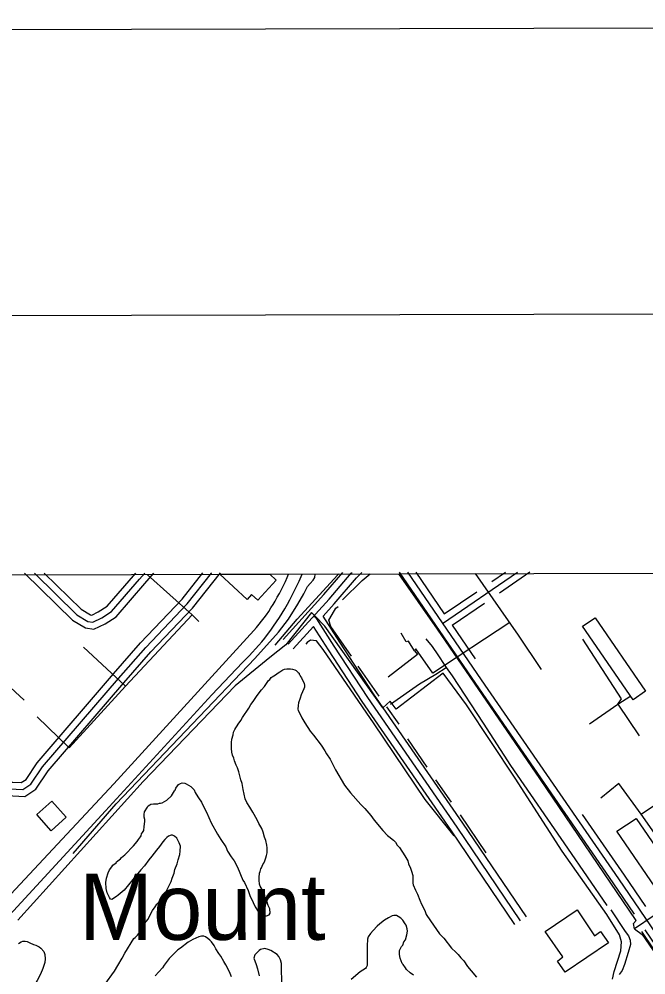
# Model space of a CAD drawing. Extents: x 3355724 to 3393621, y 594744 to 620174.
# Drawn here: x 3384041 to 3385411, y 617501 to 619590 of the extents above; entities that cross this region are included whole.
import ezdxf

# ---------------------------------------------------------------- set-up
doc = ezdxf.new("R2010")
doc.units = 0
for name, color, linetype in [('G-ANNO-NPLT', 7, 'Continuous'), ('V-ANNO-SYMB', 7, 'Continuous'), ('V-BLDG-OTLN', 7, 'Continuous'), ('V-GRID-FRAM', 7, 'Continuous'), ('V-RAIL-TRAK', 7, 'Continuous'), ('V-ROAD-CNTR', 7, 'Continuous'), ('V-SITE-OTLN', 7, 'Continuous'), ('V-SITE-VEGE', 7, 'Continuous'), ('V-TOPO-GNAM-IDEN', 7, 'Continuous'), ('V-TOPO-SHOR', 7, 'Continuous'), ('V-UTIL-LINE', 7, 'Continuous')]:
    doc.layers.add(name, color=color, linetype=linetype)

msp = doc.modelspace()

# ---------------------------------------------------------------- linework, layer by layer
at = {"layer": 'G-ANNO-NPLT'}
msp.add_lwpolyline([(3356370.8, 595327.7), (3393037.4, 595423.7), (3392974.1, 619590.2), (3356307.6, 619494.2)], close=True, dxfattribs=at)
at = {"layer": 'V-ANNO-SYMB'}
msp.add_lwpolyline([(3359119.3, 595959.9), (3392202.4, 596046.5), (3392142.4, 618963), (3359059.3, 618876.4), (3359119.3, 595959.9)], dxfattribs=at)
at = {"layer": 'V-BLDG-OTLN'}
for p, q in [((3384479.8, 618376.4), (3384480, 618376.7)), ((3384539.4, 618321.6), (3384479.8, 618376.4)), ((3384480, 618376.7), (3384589, 618376.9)), ((3384589, 618376.9), (3384603.3, 618363.8)), ((3384603.3, 618363.8), (3384562.7, 618319.7)), ((3384549.2, 618332.2), (3384539.4, 618321.6)), ((3384562.7, 618319.7), (3384549.2, 618332.2))]:
    msp.add_line(p, q, dxfattribs=at)
for points in [[(3385300.2, 618281), (3385410.4, 618121.1), (3385383.1, 618102.3), (3385272.4, 618262.9)], [(3384112.8, 617880.6), (3384144.4, 617845.3), (3384111.4, 617815.8), (3384079.8, 617851.1)], [(3385389.4, 617842.8), (3385491.7, 617694.2), (3385450.1, 617664.7), (3385347.2, 617815.1)], [(3385328.9, 617570.9), (3385234.4, 617506.5), (3385217.5, 617530.8), (3385229.4, 617539.8), (3385190.9, 617595.7), (3385261, 617642.7), (3385299, 617586.2), (3385311.5, 617595.3)]]:
    msp.add_lwpolyline(points, close=True, dxfattribs=at)
at = {"layer": 'V-GRID-FRAM'}
msp.add_lwpolyline([(3359807.6, 618312.1), (3391397.2, 618394.8), (3391452.7, 600211.2), (3359847.2, 600128.5), (3359807.6, 618312.1)], dxfattribs=at)
at = {"layer": 'V-RAIL-TRAK'}
for points in [[(3383676.2, 617348.3), (3383804.6, 617451.3), (3383824.1, 617467.9), (3383850.7, 617493.2), (3383878.8, 617523.3), (3384248.4, 617918.6), (3384554.6, 618253.8), (3384560.3, 618260.4), (3384566, 618267.2), (3384571.4, 618274), (3384576.7, 618281), (3384581.8, 618288.2), (3384586.8, 618295.4), (3384591.6, 618302.8), (3384596.2, 618310.2), (3384600.6, 618317.8), (3384605.5, 618326.2), (3384610.2, 618334.7), (3384614.7, 618343.3), (3384619, 618352.1), (3384623.2, 618360.9), (3384627.1, 618369.8), (3384630.1, 618377.1)], [(3383995.1, 617604.4), (3384230.3, 617859), (3384462.3, 618112.8), (3384529.5, 618183.9), (3384536.8, 618191.1), (3384544.1, 618198.4), (3384551.2, 618205.9), (3384558.1, 618213.5), (3384564.9, 618221.2), (3384571.6, 618229), (3384578, 618237), (3384584.4, 618245.2), (3384591.1, 618254.2), (3384597.6, 618263.3), (3384604, 618272.6), (3384610.2, 618282), (3384616.2, 618291.5), (3384622, 618301.2), (3384627.6, 618310.9), (3384633.1, 618320.7), (3384638.4, 618330.7), (3384643.4, 618340.7), (3384648.3, 618350.9), (3384653, 618361.1), (3384657.4, 618371.4), (3384659.8, 618377.1)]]:
    msp.add_lwpolyline(points, dxfattribs=at)
at = {"layer": 'V-ROAD-CNTR'}
for points in [[(3383502.6, 618377.2), (3383572.1, 618314.1), (3384020.6, 617907.3), (3384049.9, 617906), (3384067.3, 617917.3), (3384092.7, 617955.6), (3384258.8, 618148.9), (3384318, 618216.7), (3384408.7, 618312.1), (3384461.5, 618379.1), (3384462, 618379.7)], [(3383524.9, 618377.2), (3383582.2, 618325.2), (3384026.6, 617922), (3384045.7, 617921.2), (3384056.5, 617928.2), (3384080.7, 617964.6), (3384247.5, 618158.7), (3384306.9, 618226.8), (3384397.4, 618321.9), (3384442.8, 618379.6)], [(3383879.4, 618015.1), (3384014.5, 617892.5), (3384054, 617890.8), (3384078.1, 617906.5), (3384104.7, 617946.5), (3384270.2, 618139.1), (3384329.1, 618206.6), (3384420.1, 618302.2), (3384481.1, 618379.7)], [(3384053.3, 618378.6), (3384158.4, 618275.9), (3384186.7, 618259.1), (3384204.9, 618256.2), (3384229.3, 618268.5), (3384253.4, 618283.6), (3384316, 618356.1), (3384336, 618379.3)], [(3384074.7, 618378.7), (3384167.6, 618287.9), (3384191.9, 618273.5), (3384202.5, 618271.8), (3384221.9, 618281.6), (3384243.5, 618295.2), (3384304.7, 618365.9), (3384316.2, 618379.3)], [(3384096.1, 618378.7), (3384176.8, 618299.9), (3384197.1, 618287.9), (3384200.1, 618287.4), (3384214.5, 618294.7), (3384233.7, 618306.7), (3384296.4, 618379.2)], [(3384618.2, 618233.9), (3384707.4, 618332), (3384748.8, 618380.4)], [(3384629.3, 618223.8), (3384718.6, 618322), (3384767.3, 618378.9), (3384768.8, 618380.5)], [(3384705.5, 618285.2), (3384729.9, 618312.1), (3384778.3, 618368.8), (3384790.1, 618380.5)], [(3384871.9, 618380.8), (3385038.3, 618137.5), (3385338.8, 617702), (3385385.6, 617633.2)], [(3384890, 618380.8), (3385050.7, 618146), (3385351.1, 617710.5), (3385675.8, 617233.1), (3385948.8, 616834.8), (3386180.2, 616499.2)], [(3384908.1, 618380.8), (3384970.4, 618289.8)], [(3384966.5, 618269), (3385130.6, 618381.4)], [(3385074.1, 618360.9), (3385104, 618381.4)], [(3385090.9, 618336), (3385157.3, 618381.5)], [(3384970.4, 618289.8), (3385041.3, 618338.4)], [(3384987.4, 618265.1), (3385058.1, 618313.5)], [(3385137.3, 617619.2), (3384998.7, 617823.9), (3384803.6, 618106.8), (3384729.8, 618219.6), (3384686.6, 618286.8), (3384685.6, 618282.3)], [(3385149.8, 617627.6), (3385011.1, 617832.4), (3384816.1, 618115.2), (3384742.4, 618227.8), (3384705.5, 618285.2)], [(3384640.4, 618213.7), (3384684.6, 618262.3)], [(3385124.9, 617610.8), (3384986.3, 617815.4), (3384791.2, 618098.4), (3384717.2, 618211.5), (3384684.6, 618262.3)], [(3384987.4, 618265.1), (3385037.7, 618191.5)], [(3385272, 617851.5), (3385363.5, 617719), (3385410.4, 617650)], [(3385408.6, 617599.4), (3385663.4, 617224.7), (3385936.4, 616826.3), (3386031.5, 616688.4)]]:
    msp.add_lwpolyline(points, dxfattribs=at)
at = {"layer": 'V-SITE-OTLN'}
for p, q in [((3381827, 618369.7), (3388510.8, 618387.2)), ((3384680.2, 618293.3), (3384623.9, 618221.9)), ((3384687.7, 618285.5), (3384680.2, 618293.3)), ((3384709.6, 618263), (3384687.7, 618285.5)), ((3384836, 618084.7), (3384709.6, 618263)), ((3384623.9, 618221.9), (3384589.5, 618194.9)), ((3384589.5, 618194.9), (3384513.5, 618132.3)), ((3384968, 618160.1), (3384865.3, 618081.9)), ((3385019.2, 618091.2), (3384968, 618160.1)), ((3384513.5, 618132.3), (3384312.4, 617923.4)), ((3384852, 618099.2), (3384836, 618084.7)), ((3384865.3, 618081.9), (3384852, 618099.2)), ((3385125.2, 617930.7), (3385019.2, 618091.2)), ((3385228.2, 617770.8), (3385125.2, 617930.7)), ((3384312.4, 617923.4), (3384038.5, 617620.4)), ((3385325.7, 617632.9), (3385228.2, 617770.8)), ((3385353.4, 617588.4), (3385325.7, 617632.9)), ((3385357.7, 617572.9), (3385353.4, 617588.4)), ((3385356, 617553.2), (3385357.7, 617572.9)), ((3385341.9, 617508.3), (3385356, 617553.2)), ((3385337.9, 617491.6), (3385341.9, 617508.3))]:
    msp.add_line(p, q, dxfattribs=at)
at = {"layer": 'V-SITE-VEGE'}
for points in [[(3384582.5, 617662), (3384576.8, 617674.3), (3384574.5, 617681.5), (3384572.3, 617687.1), (3384568.3, 617694.3), (3384566.6, 617698.8), (3384566, 617707.7), (3384566, 617713.3), (3384566.5, 617722.8), (3384568.1, 617726.7), (3384569.8, 617732.3), (3384571.4, 617734.6), (3384574.2, 617741.8), (3384576.4, 617744.6), (3384578, 617749.7), (3384580.8, 617756.4), (3384581.9, 617761.4), (3384583.5, 617767.6), (3384583.4, 617778.7), (3384582.9, 617784.3), (3384580.6, 617794.3), (3384577.7, 617801.6), (3384574.9, 617812.7), (3384571.5, 617820.5), (3384565.3, 617831.6), (3384561.3, 617840), (3384552.3, 617856.1), (3384550, 617860), (3384545.5, 617867.3), (3384538.8, 617877.8), (3384535.4, 617885.6), (3384530.8, 617905.7), (3384528.5, 617919.1), (3384525.6, 617926.9), (3384523.3, 617938.6), (3384521.6, 617944.7), (3384518.8, 617953.6), (3384515.9, 617959.2), (3384512, 617968.6), (3384510.3, 617974.8), (3384508, 617980.9), (3384506.3, 617987.6), (3384505.7, 617995.4), (3384505.6, 618008.8), (3384506.1, 618016.1), (3384508.8, 618025.6), (3384509.9, 618031.2), (3384512.7, 618037.3), (3384514.9, 618040.7), (3384518.2, 618045.2), (3384520.4, 618049.1), (3384526, 618056.9), (3384529.8, 618063.7), (3384543.1, 618083.8), (3384547.5, 618091.7), (3384552.5, 618098.4), (3384561.9, 618111.8), (3384571.3, 618124.2), (3384577.4, 618131.5), (3384586.3, 618144.4), (3384589.1, 618146.6), (3384592.4, 618150.6), (3384594.6, 618152.2), (3384601.3, 618156.7), (3384607.4, 618160.7), (3384611.3, 618163.5), (3384617.4, 618167.4), (3384621.3, 618169.1), (3384626.3, 618169.7), (3384634.7, 618169.8), (3384638.6, 618169.2), (3384643.6, 618167.6), (3384647, 618165.9), (3384650.9, 618162.1), (3384653.2, 618160.4), (3384653.7, 618158.2), (3384654.9, 618156.5), (3384656.6, 618153.2), (3384658.8, 618150.4), (3384661.6, 618143.2), (3384664.5, 618138.1), (3384665.1, 618133.1), (3384665.1, 618129.8), (3384663.4, 618126.4), (3384657.9, 618113), (3384655.2, 618105.7), (3384651.9, 618095.1), (3384651.4, 618089.5), (3384650.3, 618081.7), (3384651.4, 618078.9), (3384655.4, 618070.5), (3384659.3, 618062.8), (3384665.5, 618051.6), (3384677.4, 618033.3), (3384684.7, 618024.9), (3384701.6, 618002.7), (3384709.5, 617990.5), (3384713.4, 617983.8), (3384721.3, 617972.1), (3384732.6, 617948.8), (3384752.3, 617915.4)], [(3384376.7, 617806.5), (3384374, 617806.5), (3384367.8, 617804.2), (3384363.9, 617800.8), (3384359.5, 617796.4), (3384355.1, 617791.3), (3384348.4, 617781.2), (3384341.8, 617773.4), (3384331.2, 617759.9), (3384324.6, 617752), (3384315.2, 617739.2), (3384307.4, 617730.7), (3384289.7, 617708.9), (3384270.8, 617685.9), (3384258.1, 617675.2), (3384254.2, 617671.8), (3384244.2, 617665.6), (3384240.8, 617666.1), (3384238.6, 617670), (3384233.5, 617680), (3384231.7, 617689.5), (3384231.1, 617702.9), (3384232.7, 617712.4), (3384236, 617723.6), (3384238.8, 617730.3), (3384243.7, 617737), (3384246.5, 617740.4), (3384253.2, 617746), (3384254.3, 617747.7), (3384263.2, 617754.5), (3384264.8, 617757.3), (3384272.1, 617763.5), (3384278.2, 617769.1), (3384286.5, 617777.5), (3384291.5, 617783.1), (3384299.2, 617792.6), (3384302.6, 617796.6), (3384304.2, 617799.4), (3384306.4, 617802.2), (3384308.1, 617805), (3384309.2, 617808.9), (3384310.8, 617811.7), (3384313.6, 617816.7), (3384314.7, 617825.1), (3384316.3, 617835.7), (3384316.2, 617840.2), (3384314.5, 617845.2), (3384314.5, 617851.3), (3384315.6, 617856.9), (3384321.7, 617867), (3384323.3, 617870.4), (3384327.2, 617872.6), (3384328.9, 617873.8), (3384335, 617874.4), (3384337.3, 617874.4), (3384342.3, 617875), (3384344.5, 617875), (3384347.9, 617876.1), (3384350.6, 617876.1), (3384354, 617876.7), (3384364, 617882.3), (3384374.6, 617891.9), (3384380.6, 617903.1), (3384382.3, 617904.8), (3384383.9, 617908.7), (3384390, 617916.6), (3384393.9, 617918.8), (3384397.8, 617920.5), (3384403.4, 617920), (3384406.8, 617918.3), (3384416.3, 617912.8), (3384423.6, 617905.6), (3384426.4, 617899.5), (3384432.1, 617890), (3384433.7, 617887.8), (3384439.9, 617878.3), (3384443.3, 617870), (3384451.2, 617856.1), (3384461.4, 617833.3), (3384475, 617808.2), (3384482.3, 617796.5), (3384493, 617780.4), (3384497, 617770.9), (3384504.9, 617758.7), (3384511.1, 617749.8), (3384518.4, 617735.9), (3384530.3, 617708.1), (3384533.7, 617702.5), (3384541.6, 617685.2), (3384545.6, 617674.1), (3384552.9, 617659.1), (3384556.9, 617649.6), (3384565.3, 617637.4), (3384572.1, 617631.8), (3384578.2, 617629.6), (3384582.1, 617629.7), (3384587.7, 617631.9), (3384589.9, 617635.9), (3384589.3, 617644.8), (3384585.9, 617652.6), (3384582.5, 617662)], [(3384752.3, 617915.4), (3384765.3, 617898.7), (3384788.3, 617873.2), (3384796.7, 617864.3), (3384810.2, 617849.3), (3384817.5, 617838.7), (3384836.1, 617816), (3384846.2, 617805.4), (3384849.6, 617803.2), (3384859.1, 617795.5), (3384863.6, 617790.5), (3384867.5, 617784.3), (3384872.6, 617779.3), (3384884.4, 617761), (3384890.6, 617749.9), (3384892.4, 617743.2), (3384896.3, 617733.7), (3384898.6, 617727.6), (3384901.4, 617718.1), (3384901.5, 617701.4), (3384902.1, 617697.5), (3384907.2, 617685.8), (3384911.7, 617677.4), (3384916.8, 617664.1)], [(3384228.5, 617479.6), (3384249.6, 617508.8), (3384256.8, 617521.1), (3384266.7, 617537.3), (3384272.2, 617548.5), (3384292.1, 617580.5), (3384294.9, 617582.2), (3384299.9, 617587.8), (3384306.6, 617595.6), (3384309.3, 617601.8), (3384315.9, 617613.6), (3384322.6, 617621.4), (3384327, 617629.8), (3384330.3, 617636.5), (3384333.1, 617641.6), (3384338.6, 617649.4), (3384342.5, 617655.6), (3384349.7, 617663.4), (3384353, 617668.5), (3384357.4, 617674.7), (3384360.2, 617678), (3384362.4, 617681.9), (3384364.6, 617687.5), (3384366.8, 617691.5), (3384373.4, 617704.9), (3384376.2, 617712.2), (3384380, 617722.8), (3384381.7, 617731.2), (3384386.6, 617743.5), (3384388.8, 617752.4), (3384392.6, 617764.2), (3384393.1, 617771.4), (3384394.2, 617782.1), (3384390.8, 617789.3), (3384386.3, 617799.9), (3384381.2, 617803.7), (3384376.7, 617806.5)], [(3384916.8, 617664.1), (3384920.8, 617655.2), (3384927.6, 617641.2), (3384931, 617632.9), (3384940, 617619), (3384960.3, 617590.6), (3384969.3, 617580.6), (3384986.1, 617559), (3384995.7, 617550.7), (3385000.7, 617545.1), (3385006.4, 617537.9), (3385013.1, 617531.2), (3385021.5, 617519), (3385028.9, 617509.5), (3385040.7, 617495.7)], [(3384903.3, 617500.4), (3384896, 617504.8), (3384888.2, 617512.1), (3384885.9, 617515.9), (3384880.3, 617523.2), (3384878.6, 617525.9), (3384874.1, 617537.1), (3384872.9, 617544.9), (3384872.8, 617553.8), (3384874.5, 617558.3), (3384876.7, 617562.8), (3384879.5, 617565.6), (3384882.2, 617572.9), (3384885.5, 617577.3), (3384888.8, 617588.5), (3384889.9, 617596.4), (3384889.3, 617601.4), (3384887, 617609.7), (3384885.3, 617612.5), (3384879.7, 617620.3), (3384875.8, 617624.7), (3384869.6, 617628.6), (3384865.7, 617630.3), (3384860.1, 617630.2), (3384856.2, 617629.6), (3384848.4, 617625.7), (3384839.5, 617620.1), (3384829.5, 617612.2), (3384824, 617607.1), (3384815.1, 617597.6), (3384809.5, 617591.4), (3384804, 617583.6), (3384802.4, 617578.5), (3384802.4, 617574.6), (3384801.9, 617568.5), (3384802.1, 617526.6), (3384801.6, 617521), (3384799.9, 617517.1), (3384798.3, 617514.9), (3384792.7, 617510.9), (3384786.6, 617507), (3384766.6, 617490.7)], [(3384039.8, 617569.3), (3384045.9, 617573.2), (3384049.2, 617574.3), (3384054.8, 617574.4), (3384059.3, 617573.3), (3384064.9, 617571.1), (3384072.7, 617567.2)], [(3384505.3, 617496.4), (3384500.8, 617507.5), (3384492.9, 617522.5), (3384488.9, 617530.3), (3384482.2, 617541.4), (3384477.7, 617547.5), (3384471.5, 617557.6), (3384467.5, 617564.8), (3384461.9, 617572.6), (3384457.9, 617576.4), (3384453.5, 617580.3), (3384448.4, 617583.7), (3384445.1, 617585.3), (3384440, 617585.3), (3384433.9, 617584.1), (3384421.1, 617577.9), (3384411.1, 617572.3), (3384393.9, 617558.8), (3384388.3, 617555.4), (3384377.2, 617544.7), (3384369.4, 617536.3), (3384358.4, 617521.7), (3384354.5, 617516.1), (3384339, 617498.7)], [(3384072.7, 617567.2), (3384077.7, 617565.6), (3384085, 617561.7), (3384088.9, 617558.9), (3384095.1, 617551.7), (3384097.4, 617545.6), (3384098.6, 617536.1), (3384097.5, 617527.7), (3384093.1, 617514.3), (3384088.2, 617502.6), (3384081, 617488.6), (3384068.8, 617467.8), (3384058.3, 617453.3), (3384050, 617440.9), (3384036.7, 617423.5)], [(3384615.4, 617474.7), (3384615.1, 617525.5), (3384612.8, 617533.3), (3384608.9, 617541.1), (3384605, 617545), (3384591.5, 617553.8), (3384585.9, 617556), (3384578.6, 617558.2), (3384569.2, 617555.9), (3384565.8, 617554.2), (3384556.4, 617544.7), (3384554.2, 617537.4), (3384559.3, 617523.5), (3384562.2, 617514), (3384565.6, 617498.9)]]:
    msp.add_lwpolyline(points, dxfattribs=at)
at = {"layer": 'V-TOPO-SHOR'}
for p, q in [((3384828.1, 618110), (3384782.5, 618175.8)), ((3384872, 618049), (3384844.9, 618086.9)), ((3384932.7, 617954.6), (3384890.6, 618016.9)), ((3384986.1, 617878.2), (3384951.9, 617927.4)), ((3385061.8, 617767.3), (3385005.9, 617850.3))]:
    msp.add_line(p, q, dxfattribs=at)
for points in [[(3384159.8, 617765.9), (3384253.2, 617874.9), (3384420.1, 618049.7), (3384556.2, 618192.3), (3384608.2, 618250.3), (3384630.1, 618278.4), (3384650.7, 618311.3), (3384663.7, 618333.4), (3384671.9, 618349.6), (3384677.2, 618356.7), (3384683.7, 618363.9), (3384687.3, 618369.3), (3384688.4, 618376.4), (3384688.4, 618377.2)], [(3384601.2, 618221.2), (3384649.1, 618278.6), (3384737.8, 618375), (3384739.9, 618377.3)], [(3384748.3, 618320.9), (3384790.9, 618362.8), (3384808.4, 618377.5)], [(3384767.5, 618197.2), (3384722.4, 618262.4), (3384718.2, 618276.1), (3384725.2, 618288.6), (3384733.5, 618302.4), (3384738.2, 618306)], [(3384991.9, 617804.9), (3384928.9, 617884.4), (3384817.2, 618049.2), (3384706, 618212.3), (3384691, 618231.2), (3384677.9, 618232.4), (3384670.8, 618227), (3384667.9, 618224)], [(3384929.8, 618235.7), (3384943.6, 618218.5), (3384956.2, 618200.1), (3384971.8, 618177), (3384974.8, 618172.8), (3384988, 618154.4), (3385055.3, 618051.2), (3385115.4, 617958.1), (3385239.8, 617777.9), (3385325.7, 617652.2)], [(3384852.6, 618092.9), (3384916.1, 618136.7), (3384952.3, 618158.4), (3384974.8, 618172.8)], [(3385334.1, 617642.7), (3385365.9, 617595.2), (3385373.1, 617585.7), (3385376.7, 617576.8), (3385377.4, 617567.3), (3385372.1, 617549.4), (3385364, 617523.2), (3385359.3, 617510.6), (3385352.2, 617501.7)], [(3385401.4, 617595.7), (3385555.4, 617366.1), (3385578.3, 617389.1)]]:
    msp.add_lwpolyline(points, dxfattribs=at)
at = {"layer": 'V-UTIL-LINE'}
for p, q in [((3384419.7, 618288.2), (3384433.9, 618273.1)), ((3385349.8, 618092.6), (3385377.7, 618110.9))]:
    msp.add_line(p, q, dxfattribs=at)
for points in [[(3384322.5, 618376.2), (3384321.6, 618375.3), (3384419.7, 618288.2)], [(3385386, 617601.3), (3385383.6, 617613), (3385390, 617619.5), (3385178.9, 617930.3), (3384955.5, 618256.8), (3384870.9, 618377.7)], [(3385182.8, 618168.1), (3385132.7, 618243.2), (3385038.6, 618378.1)], [(3384419.7, 618288.2), (3384274, 618131.9), (3384182.3, 618217.2)], [(3385113.3, 618271), (3384945.7, 618160.1), (3384908.5, 618213.6), (3384905.6, 618209.5), (3384892.1, 618230.5), (3384887.4, 618228.7), (3384876.2, 618247.9)], [(3385349.8, 618092.6), (3385357.3, 618104.3), (3385273.5, 618234.7)], [(3384905.6, 618209.5), (3384912.1, 618200.8), (3384847.5, 618151.3)], [(3384052.7, 618101.3), (3384003.3, 618147.2), (3383811.2, 617936.2), (3383610.9, 617721.2), (3383627.9, 617708.4), (3383546, 617615.6), (3383326.9, 617810.6), (3383285.1, 617767.1), (3383195.8, 617846.1), (3383149.4, 617790.3), (3383135.2, 617804.8), (3383067.9, 617734.8), (3383043.2, 617758.1), (3383025.2, 617736.3)], [(3384274, 618131.9), (3384150.9, 617997.3), (3384081, 618064.7)], [(3385770.2, 617863.1), (3385515.3, 617688.6), (3385400.3, 617852.1), (3385765.2, 618098.6)], [(3385287.5, 618049.5), (3385349.8, 618092.6), (3385396.4, 618023.3)], [(3385400.3, 617852.1), (3385352, 617919), (3385312.4, 617887.2)], [(3385515.3, 617688.6), (3385386, 617601.3), (3385403.1, 617589.2), (3385450.8, 617518.7), (3385451.4, 617515.2), (3385571.1, 617341.8), (3385577, 617337.8), (3385673.7, 617195.7), (3385453, 617051.2), (3385361.1, 617186.3), (3385223.2, 617089)]]:
    msp.add_lwpolyline(points, dxfattribs=at)

# ---------------------------------------------------------------- texts
at = {"layer": 'V-TOPO-GNAM-IDEN'}
msp.add_text('Mount', height=145, dxfattribs=at).set_placement((3384172.3, 617577.3))

doc.saveas('drawing.dxf')
